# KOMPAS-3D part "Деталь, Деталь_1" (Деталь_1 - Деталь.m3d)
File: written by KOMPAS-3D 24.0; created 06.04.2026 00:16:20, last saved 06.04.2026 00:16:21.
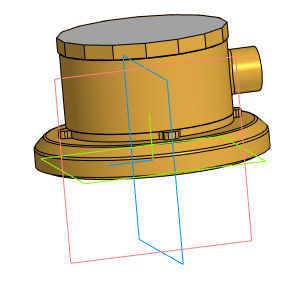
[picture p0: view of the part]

Document properties: Автор: tyuri; Полное имя файла: D:\Аутсорс\VBA0000E-T Клапан балансировочный автоматический DN.ru\DN20\Исходные файлы\Деталь_1 - Деталь.m3d

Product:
- Body: Твердое тело1  | qty 1
    Масса: 0.539214
- Part/product: Деталь  | designation Деталь_1
    Масса: 0.539214
    additional columns: Типовые

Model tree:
1. Твердое тело1  (labels: Твердое тело1)
2. Эскиз:1  (labels: Грань.Твердое тело1)
3. Элемент выдавливания:1
     Расстояние 2 = 39.8

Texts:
  Деталь_1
